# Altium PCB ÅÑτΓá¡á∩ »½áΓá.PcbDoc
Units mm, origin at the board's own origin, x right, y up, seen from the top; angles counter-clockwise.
Board outline 140 x 100 mm, 4 copper layers ([1]Top, [2]MWGND, [3]Signal, [4]Power), stack 1.271 mm thick; 48 components, 23 nets, 192 pads, 798 vias.
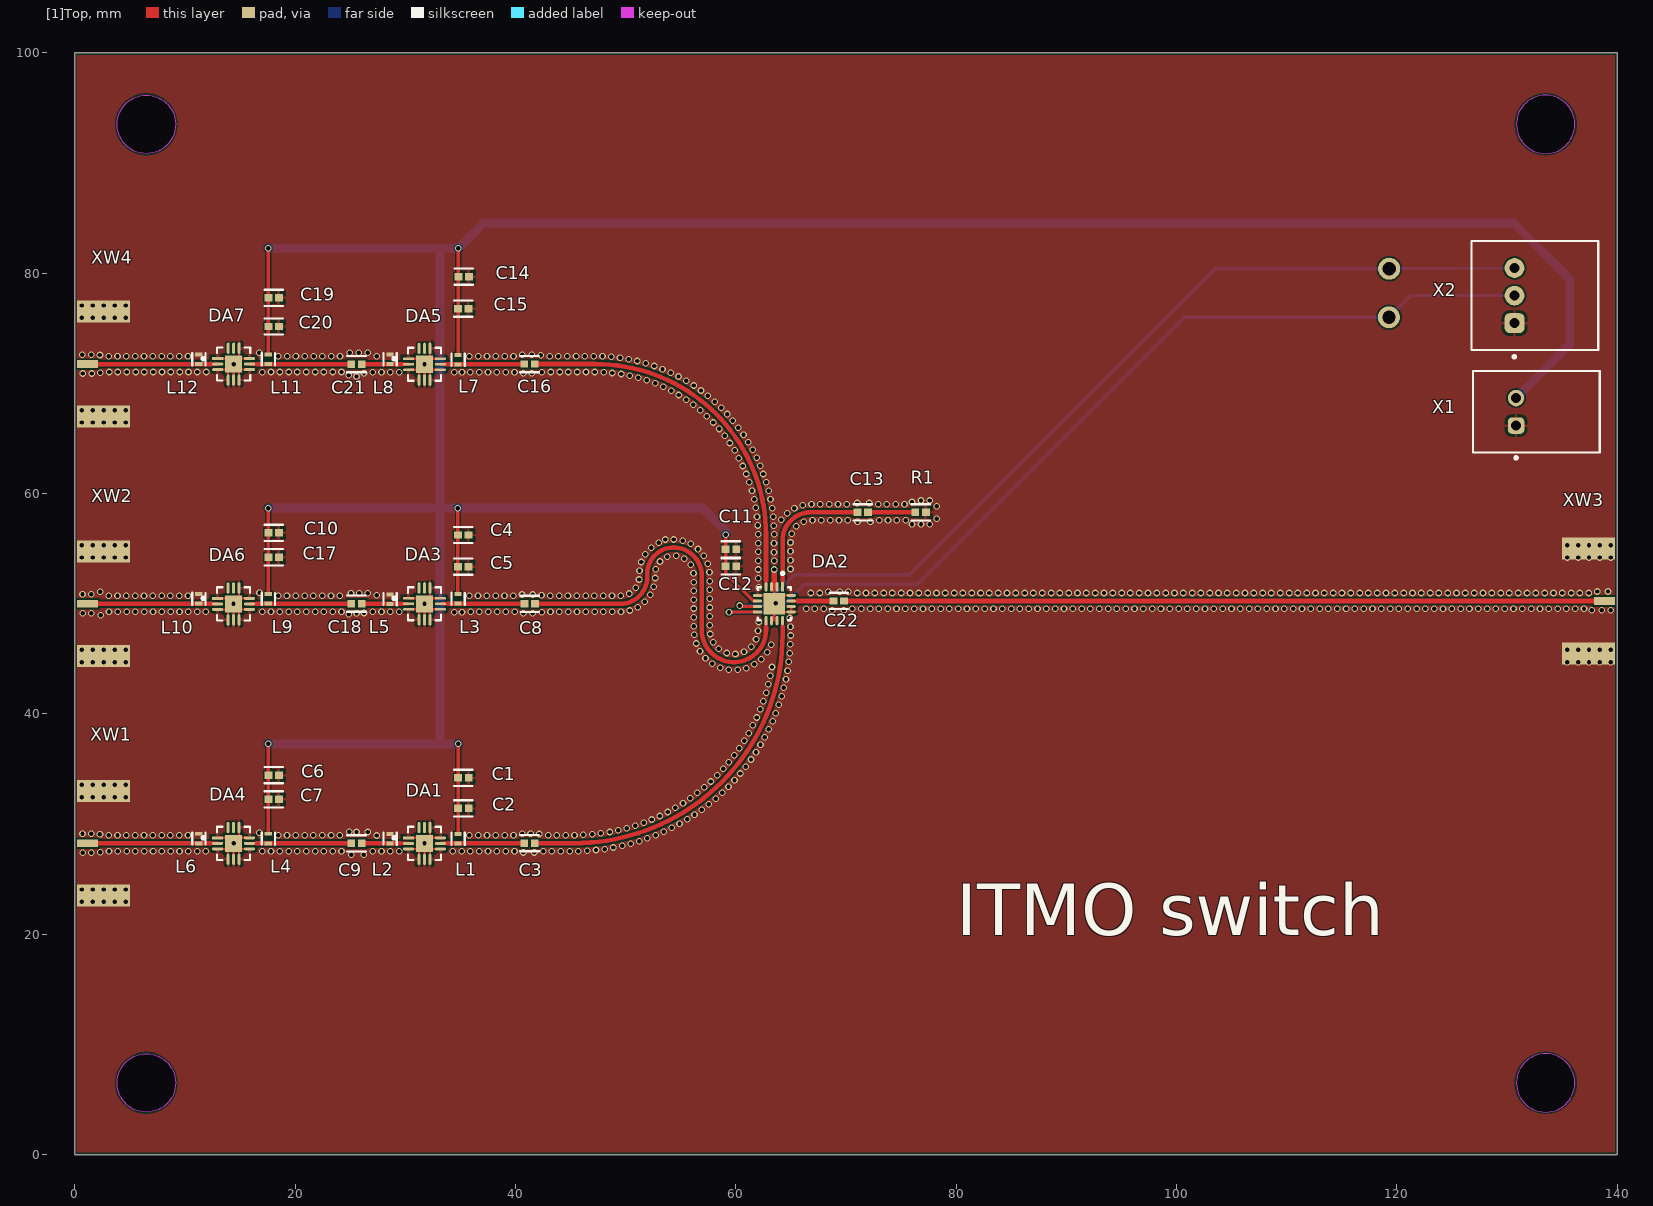
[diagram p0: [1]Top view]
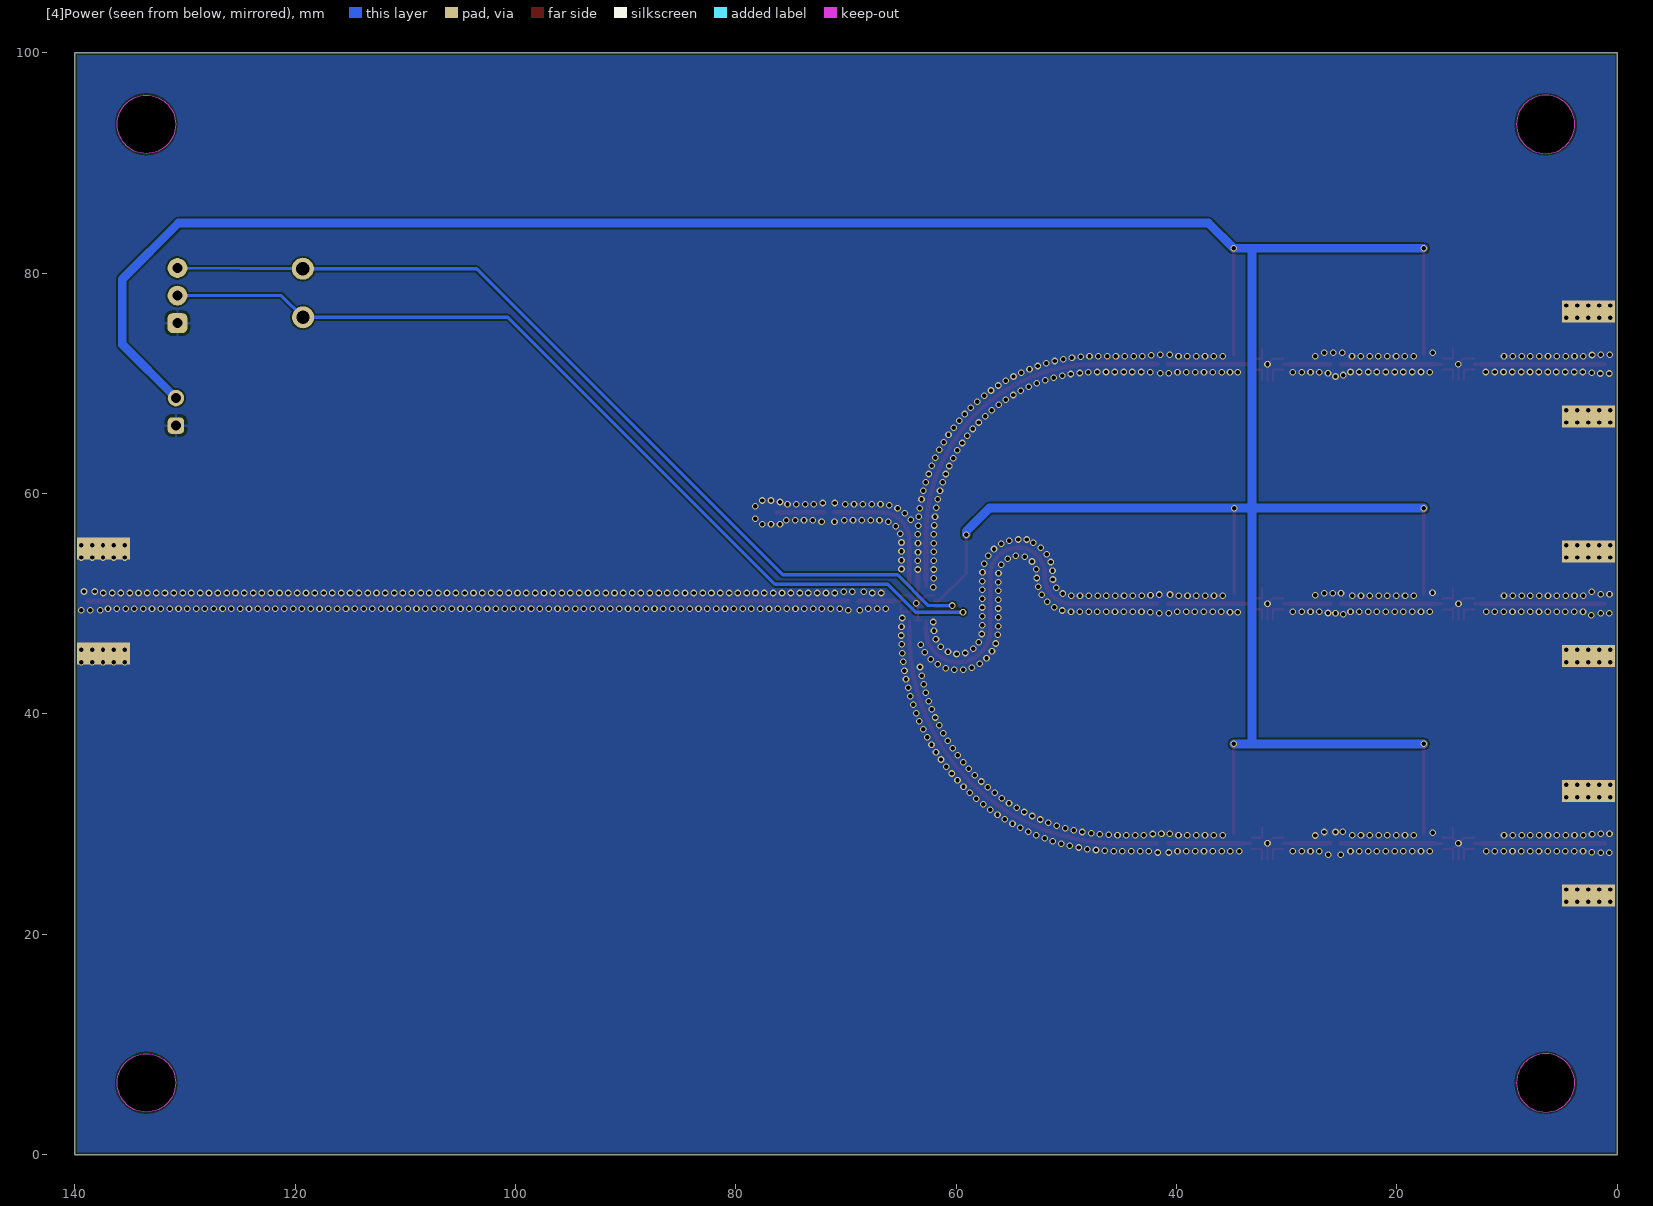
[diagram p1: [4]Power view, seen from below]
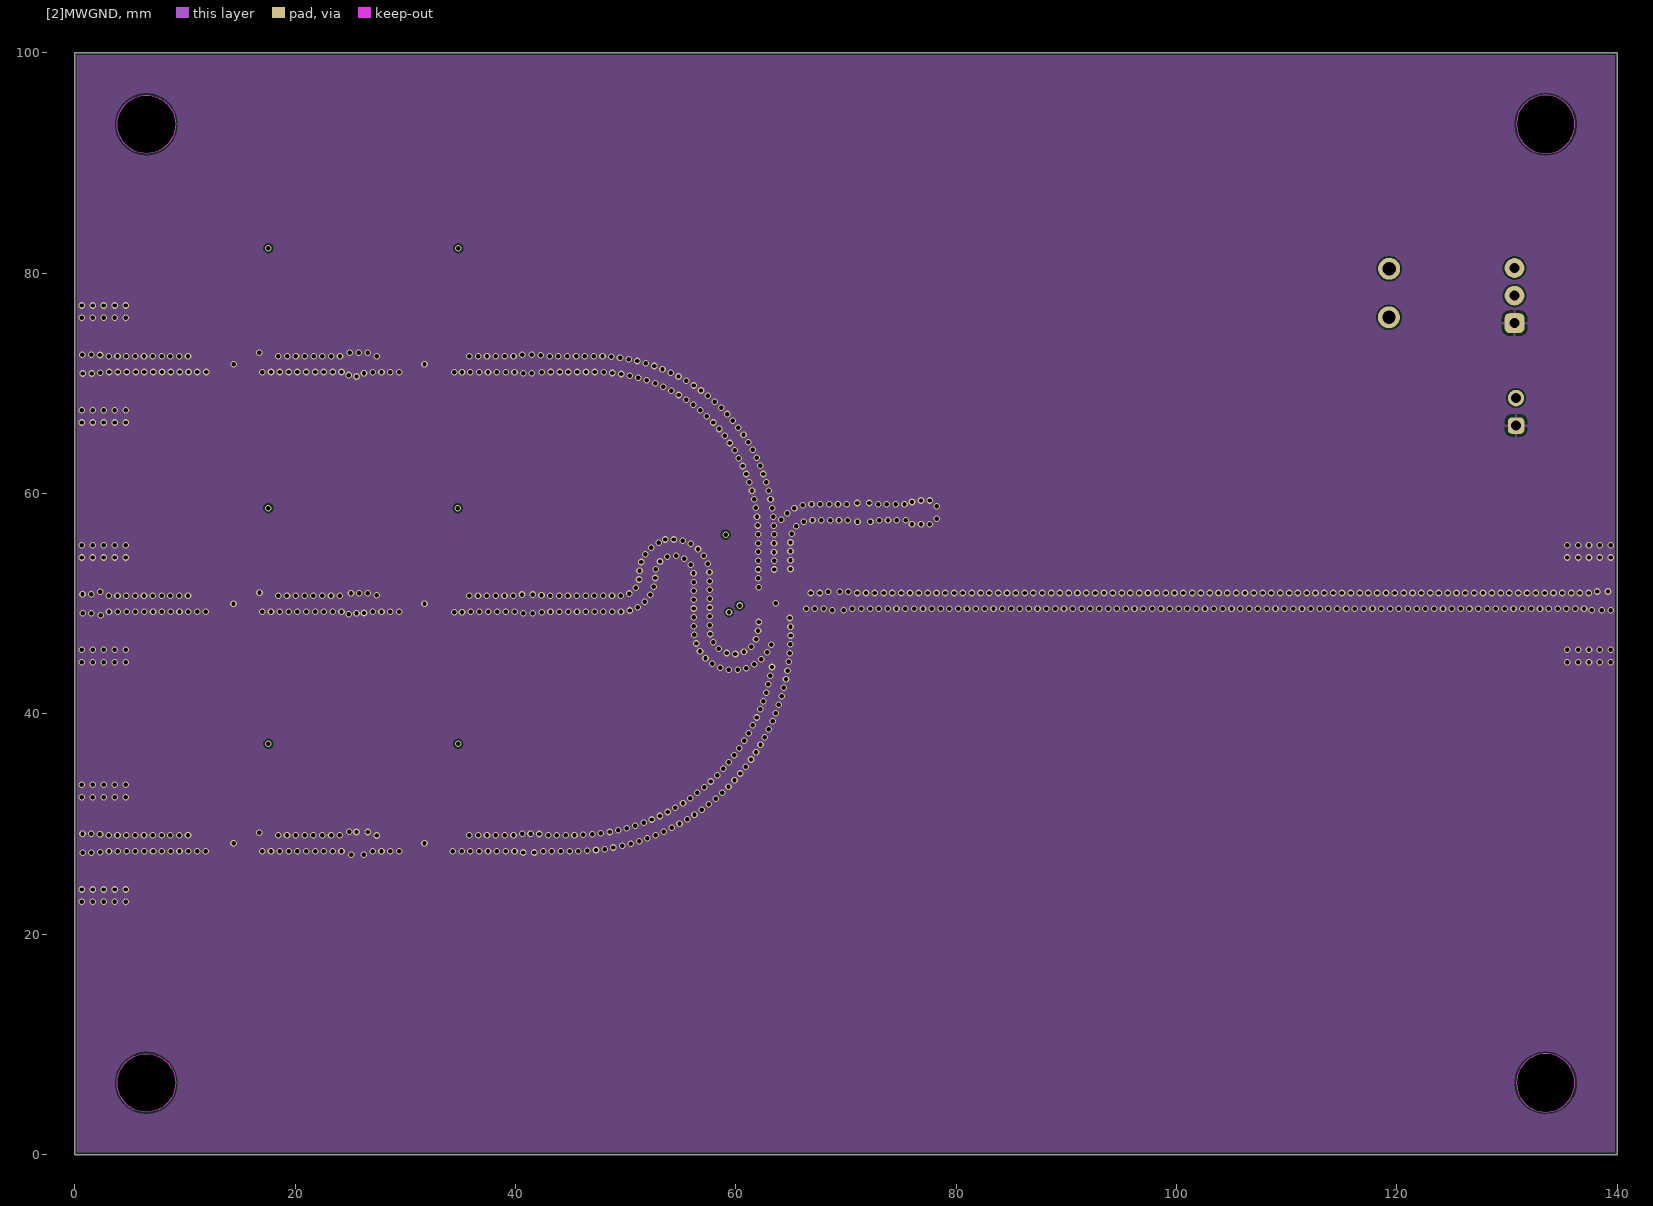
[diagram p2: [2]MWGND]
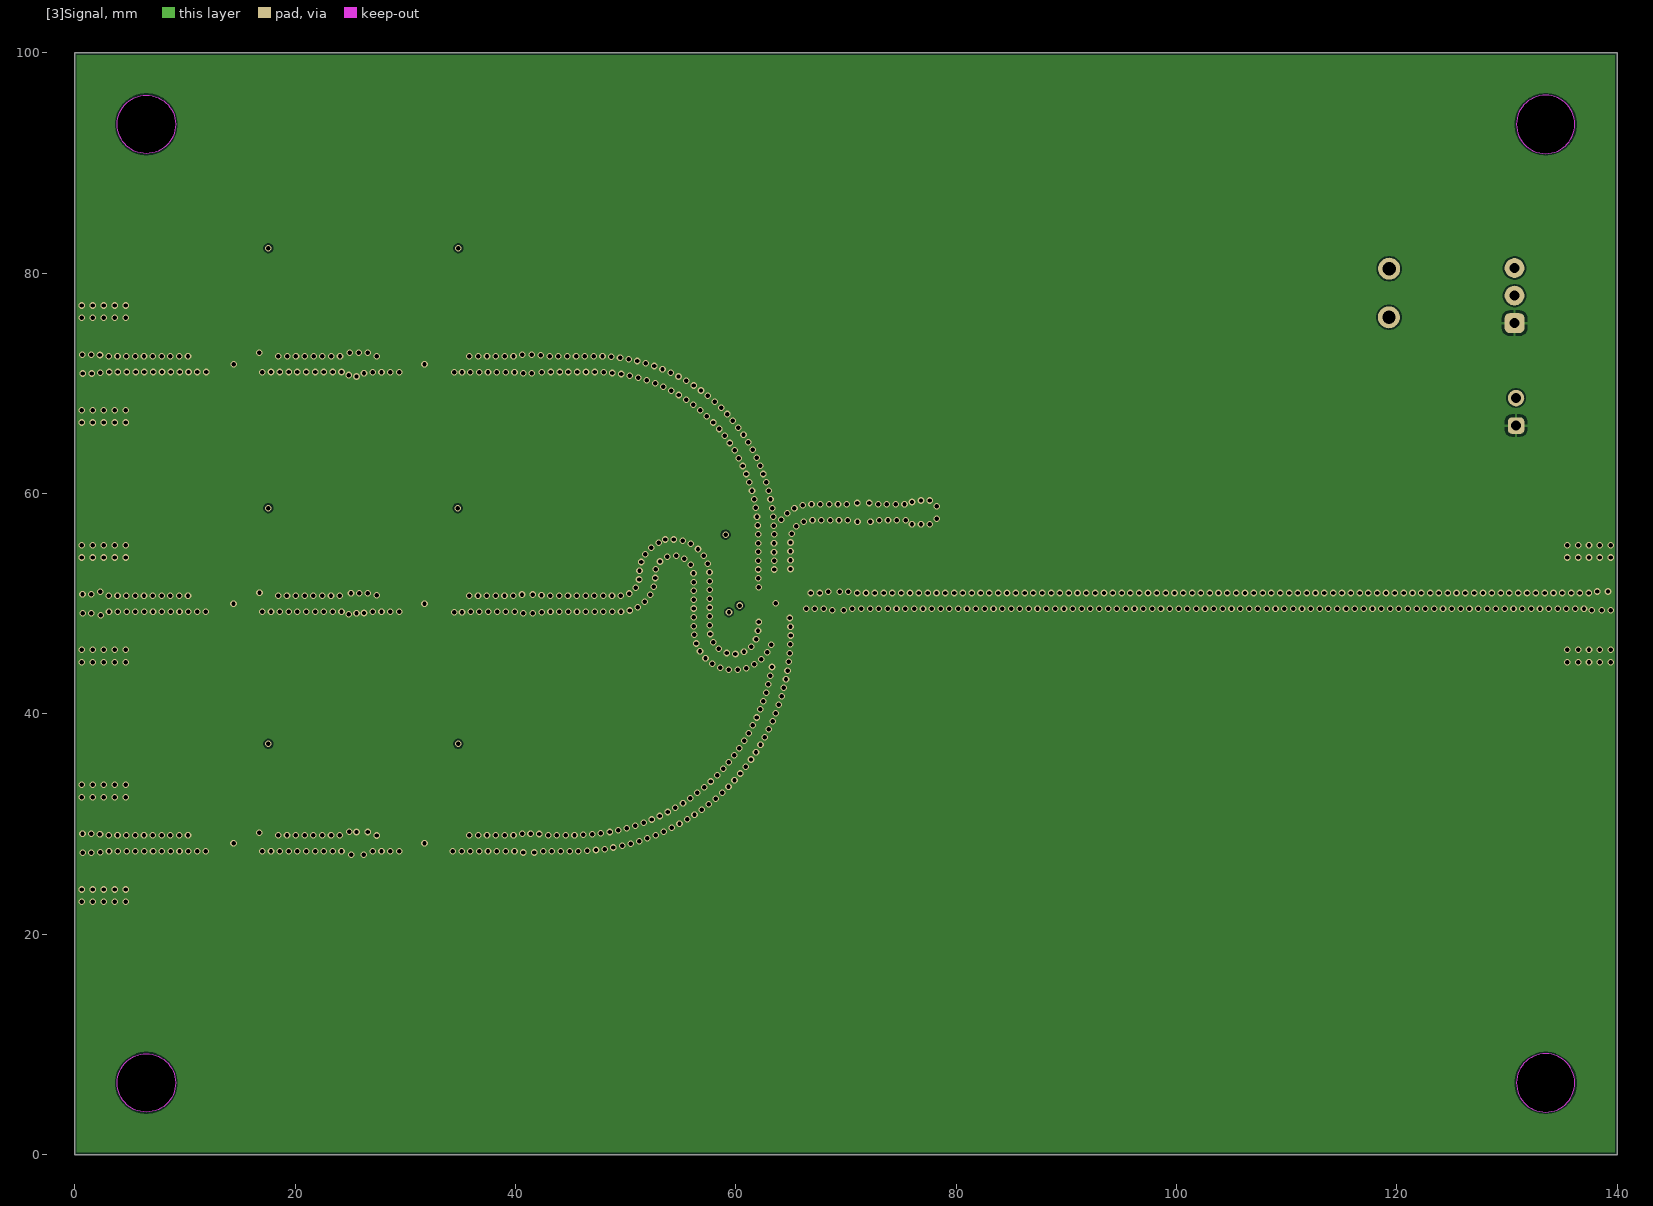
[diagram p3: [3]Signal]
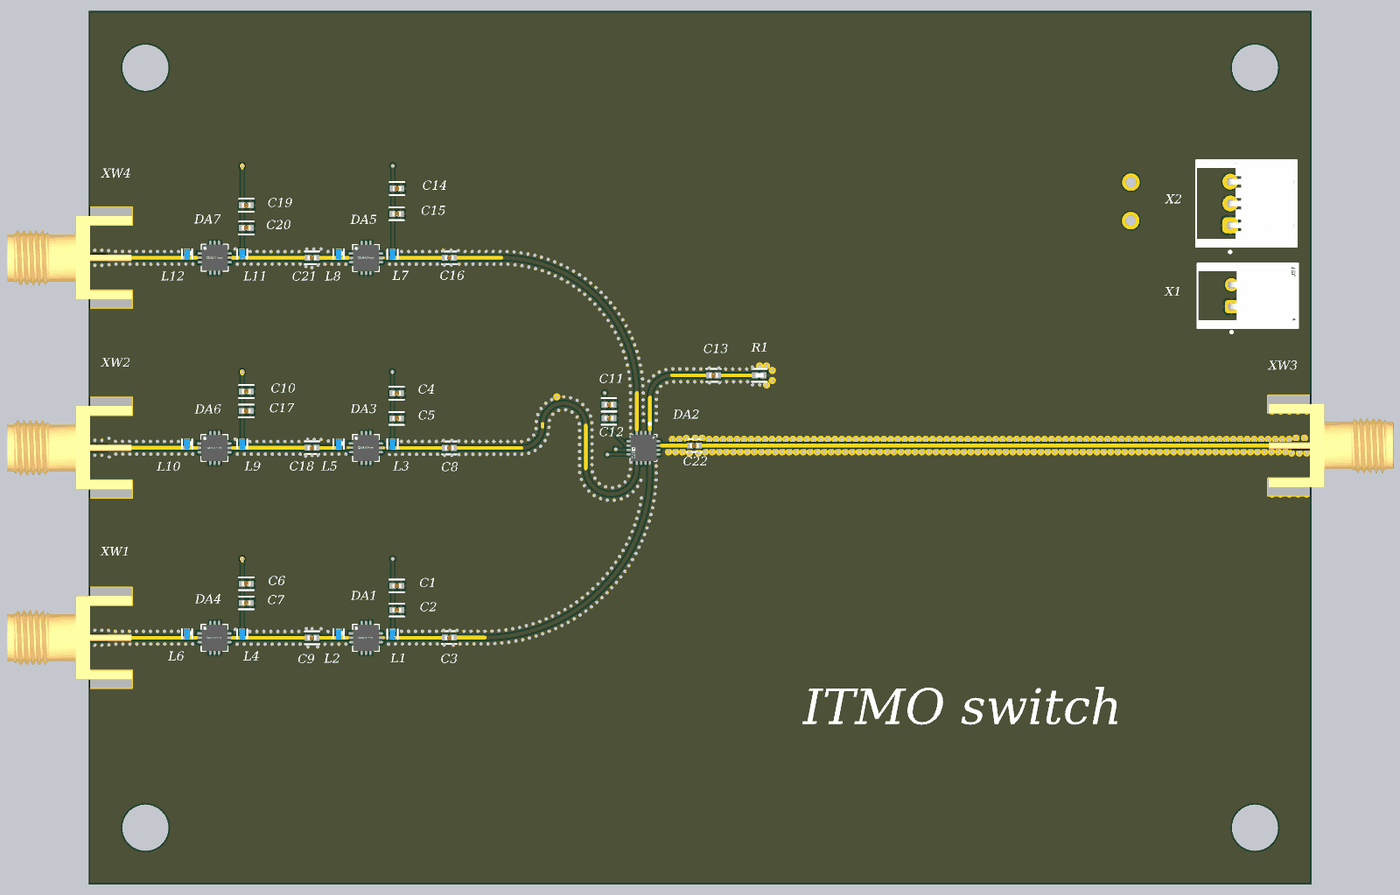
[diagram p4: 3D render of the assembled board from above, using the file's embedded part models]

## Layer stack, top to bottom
Top Solder: solder mask 0.0102, Solder Resist, Dk 3.5
[1]Top: signal copper 0.018
RO4003C: core 0.2032, Core-026, Dk 3.38
[2]MWGND: signal copper 0.018
Dielectric 1: prepreg 0.2083, PP-022, Dk 4.5
[3]Signal: signal copper 0.018
FR-4: core 0.7874, Core-040, Dk 4.6
[4]Power: signal copper 0.018
Bottom Solder: solder mask 0.0102, Solder Resist, Dk 3.5

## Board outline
0.006,0.006 140.006,0.006 140.006,100.006 0.006,100.006
cut-out: 6.506,3.856 cw(c6.506,6.506) 3.856,6.506 cw(c6.506,6.506) 6.506,9.156 cw(c6.506,6.506) 9.156,6.506 cw(c6.506,6.506)
cut-out: 130.856,6.506 ccw(c133.506,6.506) 133.506,3.856 ccw(c133.506,6.506) 136.156,6.506 ccw(c133.506,6.506) 133.506,9.156 ccw(c133.506,6.506)
cut-out: 130.856,93.506 ccw(c133.506,93.506) 133.506,90.856 ccw(c133.506,93.506) 136.156,93.506 ccw(c133.506,93.506) 133.506,96.156 ccw(c133.506,93.506)
cut-out: 6.506,90.856 cw(c6.506,93.506) 3.856,93.506 cw(c6.506,93.506) 6.506,96.156 cw(c6.506,93.506) 9.156,93.506 cw(c6.506,93.506)

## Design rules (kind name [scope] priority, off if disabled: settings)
Clearance CPWG_1 [InNetClass('RF') vs InNet('GND')] p1: gap=0.2 ignorepadtopadclearanceinfootprint=FALSE except(0.15: Arc-SMDPad Track-SMDPad SMDPad-SMDPad)
Clearance [All] p2: gap=0.15 ignorepadtopadclearanceinfootprint=FALSE
MatchedLengths lia_zochem_ti_umer [InNetClass('RF')] p1: tolerance=1 checknetsindiffpair=TRUE checkdiffpairvsdiffpair=FALSE checkxsignals=FALSE checkothers=FALSE
MinimumSolderMaskSliver [All] p1: minsoldermaskwidth=0.15
PolygonConnect RF_COMPONENTS [(HasFootprint('S-P2152-19CQA') OR HasFootprint('FP-0402HP-MFG')) vs InNet('GND')] p1: connectstyle=Direct reliefconductorwidth=0.254 reliefentries=4 polygonreliefangle="90 Angle" airgapwidth=0.15
PolygonConnect [All] p2: thpad.connectstyle=Relief thpad.reliefconductorwidth=0.254 thpad.reliefentries=4 thpad.polygonreliefangle="90 Angle" thpad.airgapwidth=0.254 smdpad.connectstyle=Relief smdpad.reliefconductorwidth=0.254 smdpad.reliefentries=4 smdpad.polygonreliefangle="90 Angle" smdpad.airgapwidth=0.254 via.connectstyle=Direct via.reliefconductorwidth=0.254 via.reliefentries=4 via.polygonreliefangle="90 Angle" via.airgapwidth=0.254
RoutingVias [All] p1: holewidth=0.4 width=0.6 viastyle="Through Hole" minholewidth=0.3 minwidth=0.5 maxholewidth=0.711 maxwidth=1
SolderMaskExpansion CPWG [InNetClass('RF')] p1: expansion=1 istentingtop=FALSE
SolderMaskExpansion [All] p2: expansion=0.102 istentingtop=FALSE
SupplyNets "Schematic Supply Nets_1" [InNet('+5')] p1: voltage=0.000
SupplyNets "Schematic Supply Nets" [InNet('GND')] p2: voltage=0.000
Width micro_strip [InNetClass('RF')] p1: maxlimit=0.5 minlimit=0.254 preferedwidth=0.254 toplayer_minwidth=0.418 toplayer_maxwidth=0.418 toplayer_prefwidth=0.418 impedanceprofiledriven=TRUE impedanceprofileid={426BE0D7-A08D-4F41-A99D-DD10C29EF04F} impedanceprofilevalue=50.000000 minimp=50.000000 maximp=50.000000 favimp=50.000000 checkconnectedcopper=TRUE
Width [All] p2: maxlimit=0.8 minlimit=0.2 preferedwidth=0.3
29 further rules are at their usual default settings.

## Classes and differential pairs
net class RF_SAME: NetC3_1 NetC8_1 NetC9_2 NetC18_2 NetC21_1 NetDA7_2
net class RF: NetC3_1 NetC3_2 NetC8_1 NetC8_2 NetC9_1 NetC9_2 NetC13_1 NetC13_2 NetC16_1 NetC16_2 NetC18_1 NetC18_2 NetC21_1 NetC21_2 NetC22_1 NetC22_2 NetDA4_2 NetDA6_2 NetDA7_2
component class AMP4: XW3
component class AMP3: DA5 XW4
component class AMP2: DA3 XW2
component class AMP1: DA1 DA4 DA6 DA7 XW1

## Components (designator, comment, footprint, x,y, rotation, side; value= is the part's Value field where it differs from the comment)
C1 "10pF" FP-GJM155-0_05-IPC_A 35.285,34.186 r0 top
C2 "10nF" FP-GJM155-0_05-IPC_A 35.285,31.417 r0 top
C3 "100 pF" FP-GJM155-0_05-IPC_A 41.279,28.268 r180 top
C4 "10pF" FP-GJM155-0_05-IPC_A 35.259,56.233 r0 top
C5 "10nF" FP-GJM155-0_05-IPC_A 35.259,53.363 r0 top
C6 "10pF" FP-GJM155-0_05-IPC_A 18.057,34.434 r0 top
C7 "10nF" FP-GJM155-0_05-IPC_A 18.057,32.244 r0 top
C8 "100pF" FP-GJM155-0_05-IPC_A 41.296,49.985 r180 top
C9 "100 pF" FP-GJM155-0_05-IPC_A 25.578,28.251 r180 top
C10 "10pF" FP-GJM155-0_05-IPC_A 18.057,56.437 r0 top
C11 "10 nF" FP-GJM155-0_05-IPC_A 59.563,54.938 r180 top
C12 "10 pF" FP-GJM155-0_05-IPC_A 59.563,53.388 r180 top
C13 "100pF" FP-GJM155-0_05-IPC_A 71.526,58.291 r180 top
C14 "10pF" FP-GJM155-0_05-IPC_A 35.302,79.677 r0 top
C15 "10nF" FP-GJM155-0_05-IPC_A 35.259,76.782 r0 top
C16 "100pF" FP-GJM155-0_05-IPC_A 41.279,71.753 r180 top
C17 "10nF" FP-GJM155-0_05-IPC_A 18.057,54.217 r0 top
C18 "100 pF" FP-GJM155-0_05-IPC_A 25.578,50 r180 top
C19 "10pF" FP-GJM155-0_05-IPC_A 18.057,77.764 r0 top
C20 "10nF" FP-GJM155-0_05-IPC_A 18.057,75.16 r0 top
C21 "100 pF" FP-GJM155-0_05-IPC_A 25.578,71.75 r180 top
C22 "100 pF" FP-GJM155-0_05-IPC_A 69.342,50.25 r180 top
DA1 "PMA3-83LN+" FP-DQ1225-IPC_A#1 31.751,28.25 r0 top
DA2 "HMC7992" FP-CP-16-38-IPC_A 63.5,50 r270 top
DA3 "PMA3-83LN+" FP-DQ1225-IPC_A#2 31.751,49.993 r0 top
DA4 "PMA3-83LN+" FP-DQ1225-IPC_A#3 14.42,28.251 r0 top
DA5 "PMA3-83LN+" FP-DQ1225-IPC_A#1 31.751,71.735 r0 top
DA6 "PMA3-83LN+" FP-DQ1225-IPC_A#2 14.419,49.987 r0 top
DA7 "PMA3-83LN+" FP-DQ1225-IPC_A#3 14.428,71.747 r0 top
L1 "39 nH" FP-0402HP-MFG#1 34.798,28.671 r90 top
L2 "18nH" FP-0402HP-MFG#1 28.626,28.677 r270 top
L3 "39nH" FP-0402HP-MFG#1 34.798,50.439 r90 top
L4 "39 nH" FP-0402HP-MFG#1 17.579,28.686 r90 top
L5 "18nF" FP-0402HP-MFG#1 28.626,50.417 r270 top
L6 "18nH" FP-0402HP-MFG#1 11.268,28.686 r270 top
L7 "39nH" FP-0402HP-MFG#1 34.798,72.156 r90 top
L8 "18nH" FP-0402HP-MFG#1 28.626,72.181 r270 top
L9 "39 nH" FP-0402HP-MFG#1 17.579,50.435 r90 top
L10 "18nH" FP-0402HP-MFG#1 11.268,50.435 r270 top
L11 "39 nH" FP-0402HP-MFG#2 17.579,72.185 r90 top
L12 "18nH" FP-0402HP-MFG#1 11.268,72.185 r270 top
R1 "100" FP-CR0402-IPC_A 76.775,58.291 r180 top
X1 "JST-2P" FP-S2B-XH-A-1_LF_SN-MFG 132.67,67.415 r270 top
X2 "JST-3P" FP-S3B-XH-A-1_LF_SN-MFG 132.535,77.965 r270 top
XW1 "SMA" S-P2152-19CQA 2.6,33 r180 top
XW2 "SMA" S-P2152-19CQA 2.6,54.75 r180 top
XW3 "SMA" S-P2152-19CQA 137.4,45.5 r0 top
XW4 "SMA" S-P2152-19CQA 2.6,76.5 r180 top

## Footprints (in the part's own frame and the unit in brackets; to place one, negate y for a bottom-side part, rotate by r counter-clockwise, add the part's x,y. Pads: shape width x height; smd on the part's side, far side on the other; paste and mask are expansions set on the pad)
FP-0402HP-MFG#1 [mm]
  rect 0.36x0.66 smd paste+0 mask+0: 1(-0.435,0) 2(0.435,0)
  silkscreen extent -0.56,-0.6 0.55,0.6, body extent -0.71,-0.46 0.71,0.46, height 0.25
FP-0402HP-MFG#2 [mm]
  rect 0.36x0.66 smd paste+0: 1(-0.435,0)
  rect 0.36x0.66 smd paste+0 mask+0: 2(0.435,0)
  silkscreen extent -0.56,-0.6 0.55,0.6, body extent -0.71,-0.46 0.71,0.46, height 0.25
FP-CP-16-38-IPC_A [mm]
  rect 0.846x0.242 smd paste+0 mask+0: 1(-1.533,0.75)
  rrect100% 0.846x0.242 smd paste+0 mask+0: 2(-1.533,0.25) 3(-1.533,-0.25) 4(-1.533,-0.75) 9(1.533,-0.75) 10(1.533,-0.25) 11(1.533,0.25) 12(1.533,0.75)
  rrect100% 0.242x0.846 smd paste+0 mask+0: 5(-0.75,-1.533) 6(-0.25,-1.533) 7(0.25,-1.533) 8(0.75,-1.533) 13(0.75,1.533) 14(0.25,1.533) 15(-0.25,1.533) 16(-0.75,1.533)
  rect 1.92x1.92 smd paste-1000 mask+0: 17(0,0)
  silkscreen extent -2.88,-1.5 1.5,1.5, body extent -2.46,-2.46 2.46,2.46, height 0.25
FP-CR0402-IPC_A [mm]
  rect 0.715x0.672 smd paste+0 mask+0: 1(-0.479,0) 2(0.479,0)
  silkscreen extent -0.84,-0.74 0.84,0.74, body extent -1.04,-0.54 1.04,0.54, height 0.25
FP-DQ1225-IPC_A#1 [mm]
  rect 1.019x0.262 smd paste+0 mask+0: 1(-1.447,0.5)
  rrect100% 1.019x0.262 smd paste+0: 2(-1.447,0)
  rrect100% 1.019x0.262 smd paste+0 mask+0: 3(-1.447,-0.5) 7(1.447,-0.5) 8(1.447,0) 9(1.447,0.5)
  rrect100% 0.262x1.019 smd paste+0 mask+0: 4(-0.5,-1.447) 5(0,-1.447) 6(0.5,-1.447) 10(0.5,1.447) 11(0,1.447) 12(-0.5,1.447)
  rect 1.549x1.549 smd paste-1000 mask+0: 13(0,0)
  silkscreen extent -2.88,-1.5 1.5,1.5, body extent -2.46,-2.46 2.46,2.46, height 0.25
FP-DQ1225-IPC_A#2 [mm]
  rect 1.019x0.262 smd paste+0 mask+0: 1(-1.447,0.5)
  rrect100% 1.019x0.262 smd paste+0 mask+0: 2(-1.447,0) 3(-1.447,-0.5) 7(1.447,-0.5) 8(1.447,0) 9(1.447,0.5)
  rrect100% 0.262x1.019 smd paste+0 mask+0: 4(-0.5,-1.447) 5(0,-1.447) 6(0.5,-1.447) 10(0.5,1.447) 11(0,1.447) 12(-0.5,1.447)
  rect 1.549x1.549 smd paste-1000 mask+0: 13(0,0)
  silkscreen extent -2.88,-1.5 1.5,1.5, body extent -2.46,-2.46 2.46,2.46, height 0.25
FP-DQ1225-IPC_A#3 [mm]
  rect 1.019x0.262 smd paste+0 mask+0: 1(-1.447,0.5)
  rrect100% 1.019x0.262 smd paste+0: 2(-1.447,0) 8(1.447,0)
  rrect100% 1.019x0.262 smd paste+0 mask+0: 3(-1.447,-0.5) 7(1.447,-0.5) 9(1.447,0.5)
  rrect100% 0.262x1.019 smd paste+0 mask+0: 4(-0.5,-1.447) 5(0,-1.447) 6(0.5,-1.447) 10(0.5,1.447) 11(0,1.447) 12(-0.5,1.447)
  rect 1.549x1.549 smd paste-1000 mask+0: 13(0,0)
  silkscreen extent -2.88,-1.5 1.5,1.5, body extent -2.46,-2.46 2.46,2.46, height 0.25
FP-GJM155-0_05-IPC_A [mm]
  rect 0.715x0.672 smd paste+0 mask+0: 1(-0.479,0) 2(0.479,0)
  silkscreen extent -0.84,-0.74 0.84,0.74, body extent -1.04,-0.54 1.04,0.54, height 0.25
FP-S2B-XH-A-1_LF_SN-MFG [mm]
  rrect50% 1.5x1.5 hole 0.9 paste-2539.97 mask+0: 1(1.25,-1.85)
  round 1.5 hole 0.9 paste-2539.97 mask+0: 2(-1.25,-1.85)
  silkscreen extent -3.7,-5.75 4.3,5.75, body extent -3.8,-5.85 3.8,5.85, height 0.25
FP-S3B-XH-A-1_LF_SN-MFG [mm]
  rrect50% 1.8x1.8 hole 0.9 paste-2539.97 mask+0: 1(2.5,-1.85)
  round 1.8 hole 0.9 paste-2539.97 mask+0: 2(0,-1.85) 3(-2.5,-1.85)
  silkscreen extent -4.95,-5.75 5.67,5.75, body extent -5.05,-5.85 5.05,5.85, height 0.25
S-P2152-19CQA [mm]
  rect 1.9x0.7 smd: 1(1.45,4.75)
  rect 4.8x2 smd: 2(0,9.5) 2(0,0)
  rect 4.8x2 smd far side: 2(0,9.5) 2(0,0)
  body extent -2.34,-0.02 11.94,9.51, height 4.8

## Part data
C1 C2 C3 C4 C5 C6 C7 C8 C9 C10 C11 C12 C13 C14 C15 C16 C17 C18 C19 C20 C21 C22: library part C
L1 L2 L3 L4 L5 L6 L7 L8 L9 L10 L11 L12: library part L
R1: library part R
X1 X2: "JST type connector"

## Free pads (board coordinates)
  round 2 hole 1.2 paste-2539.97 mask+0: MH5(119.305,80.405) MH6(119.28,75.995)

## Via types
v1: diameter 0.6, hole 0.4, [1]Top to [4]Power, 792 vias
v2: diameter 0.6, hole 0.4, [1]Top to [4]Power, tented both sides, 6 vias

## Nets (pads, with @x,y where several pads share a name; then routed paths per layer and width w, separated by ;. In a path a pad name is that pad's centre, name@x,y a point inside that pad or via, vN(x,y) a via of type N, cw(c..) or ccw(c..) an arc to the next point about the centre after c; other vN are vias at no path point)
+5: C1.1 C2.1 C4.1 C5.1 C6.1 C7.1 C10.1 C11.2 C12.2 C14.1 C15.1 C17.1 C19.1 C20.1 DA2.6 L1.2 L3.2 L4.2 L7.2 L9.2 L11.2 X1.2 | length 297.6
  [1]Top w0.3: L4.2 v1(17.579,37.275) ; L9.2 v1(17.579,58.675) ; L11.2 v1(17.579,82.26) ; v2(34.765,58.675) 34.782,58.659 34.782,50.89 L3.2 ; L1.2 34.807,29.115 34.807,37.267 v2(34.815,37.275) ; L7.2 34.811,72.603 34.811,82.247 v2(34.823,82.26) ; v2(59.084,56.268) C11.2 59.084,52.735 61.569,50.25 DA2.6
  [4]Power w0.8: v1(17.579,37.275) 33.15,37.275 ; v1(17.579,58.675) 33.15,58.675 ; v1(17.579,82.26) 33.15,82.26 ; v2(34.815,37.275) 33.15,37.275 ; v2(59.084,56.268) 59.084,56.581 56.99,58.675 v2(34.765,58.675) 33.15,58.675 ; X1.2 135.695,73.54 135.695,79.445 130.583,84.557 37.12,84.557 v2(34.823,82.26) 33.15,82.26 ; 33.15,37.275 33.15,58.675 ; 33.15,58.675 33.15,82.26
A: DA2.8 pad.MH6 X2.2 | length 85.8
  [1]Top w0.254: v2(59.385,49.223) 59.407,49.244 61.961,49.244 DA2.8
  [4]Power w0.3: v2(59.385,49.223) 63.679,49.223 66.221,51.765 76.455,51.765 100.685,75.995 pad.MH6 121.25,77.965 X2.2
B: DA2.7 pad.MH5 X2.3 | length 84.6
  [1]Top w0.254: v2(60.35,49.832) 60.444,49.832 60.526,49.75 DA2.7
  [4]Power w0.3: v2(60.35,49.832) 62.534,49.832 65.327,52.625 75.76,52.625 103.54,80.405 pad.MH5 X2.3
GND: C1.2 C2.2 C4.2 C5.2 C6.2 C7.2 C10.2 C11.1 C12.1 C14.2 C15.2 C17.2 C19.2 C20.2 DA1.1 DA1.3 DA1.4 DA1.5 DA1.6 DA1.7 DA1.9 DA1.10 DA1.13 DA2.2 DA2.3 DA2.5 DA2.10 DA2.11 DA2.13 DA2.14 DA2.16 DA2.17 DA3.1 DA3.3 DA3.4 DA3.5 DA3.6 DA3.7 DA3.9 DA3.10 DA3.13 DA4.1 DA4.3 DA4.4 DA4.5 DA4.6 DA4.7 DA4.9 DA4.10 DA4.13 DA5.1 DA5.3 DA5.4 DA5.5 DA5.6 DA5.7 DA5.9 DA5.10 DA5.13 DA6.1 DA6.3 DA6.4 DA6.5 DA6.6 DA6.7 DA6.9 DA6.10 DA6.13 DA7.1 DA7.3 DA7.4 DA7.5 DA7.6 DA7.7 DA7.9 DA7.10 DA7.13 L2.1 L5.1 L6.1 L8.1 L10.1 L12.1 R1.1 X1.1 X2.1 XW1.2 XW2.2 XW3.2 XW4.2 | length 66.3
  [1]Top w0.2: DA6.3 13.919,49.487 DA6.4 ; DA6.1 13.919,50.487 v1(14.419,49.987) ; DA4.3 DA4.13@13.92,27.751 ; DA4.1 13.92,28.751 v1(14.42,28.251) ; DA7.3 13.928,71.247 DA7.4 ; DA7.1 13.928,72.247 v1(14.428,71.747) DA7.5 ; DA4.4 DA4.13@13.92,27.751 ; DA6.5 v1(14.419,49.987) ; DA4.5 v1(14.42,28.251) ; DA6.6 DA6.13@14.919,49.487 ; DA6.10 14.919,50.487 DA6.9 ; DA4.6 DA4.13@14.92,27.751 ; DA4.10 DA4.13@14.92,28.751 ; DA7.6 14.928,71.247 DA7.7 ; DA7.10 14.928,72.247 DA7.9 ; DA6.7 DA6.13@14.919,49.487 ; DA4.7 DA4.13@14.92,27.751 ; DA4.9 DA4.13@14.92,28.751 ; DA1.3 31.251,27.75 DA1.4 ; DA1.1 31.251,28.75 v1(31.751,28.25) DA1.5 ; DA3.3 31.251,49.493 DA3.4 ; DA3.1 31.251,50.493 v1(31.751,49.993) DA3.5 ; DA5.3 31.251,71.235 DA5.4 ; DA5.1 31.251,72.235 v1(31.751,71.735) DA5.5 ; DA1.6 32.251,27.75 DA1.7 ; DA1.10 32.251,28.75 DA1.9 ; DA3.6 32.251,49.493 DA3.7 ; DA3.10 32.251,50.493 DA3.9 ; DA5.6 32.251,71.235 DA5.7 ; DA5.10 32.251,72.235 DA5.9 ; DA2.5 62.75,50.75 DA2.17 64.25,50.75 DA2.16 ; DA2.10 63.5,48.467 ; DA2.17@63.5,49.892 63.5,48.467 ; DA2.17@63.5,50.185 63.5,51.533 ; DA2.17@63.554,49.946 64.25,49.25 DA2.13 DA2.14 ; DA2.11 63.5,48.467 ; DA4.13@13.92,27.751 v1(14.42,28.251) ; v1(14.419,49.987) DA6.13@14.919,49.487 ; v1(14.42,28.251) DA4.13@14.92,27.751 ; v1(14.42,28.251) DA4.13@14.92,28.751
  [1]Top w0.5: 63.5,51.533 v1(63.5,53.104)
  other v1: 0.66,22.946 1.651,22.946 2.642,22.946 3.632,22.946 4.623,22.946 0.66,24.064 1.651,24.064 2.642,24.064 3.632,24.064 4.623,24.064 25.099,27.222 26.233,27.222 0.72,27.39 1.52,27.39 2.318,27.445 40.71,27.422 41.727,27.422 27.049,27.519 27.849,27.519 3.114,27.527 3.914,27.527 4.714,27.527 5.514,27.527 6.314,27.527 7.114,27.527 7.914,27.527 8.714,27.527 9.514,27.527 10.314,27.527 11.114,27.527 11.914,27.532 17.018,27.524 17.818,27.528 18.618,27.528 19.418,27.528 20.218,27.528 21.018,27.528 21.818,27.528 22.618,27.528 23.418,27.528 24.218,27.528 28.649,27.524 29.449,27.527 34.318,27.527 35.118,27.536 35.918,27.536 36.718,27.536 37.518,27.536 38.318,27.536 39.118,27.536 39.918,27.536 42.517,27.545 43.317,27.545 44.117,27.545 44.917,27.545 45.717,27.55 46.517,27.578 47.314,27.647 48.109,27.732 48.897,27.872 49.682,28.025 50.457,28.223 51.225,28.446 51.985,28.698 27.404,28.965 3.089,28.973 3.889,28.973 4.689,28.973 5.489,28.973 6.289,28.973 7.089,28.973 7.889,28.973 8.689,28.973 9.489,28.973 10.289,28.973 18.47,28.974 19.27,28.974 20.07,28.974 20.87,28.974 21.67,28.974 22.47,28.974 23.27,28.974 24.07,28.974 35.825,28.982 36.625,28.982 37.425,28.982 38.225,28.982 39.025,28.982 39.825,28.982 42.968,28.991 43.768,28.991 44.568,28.991 45.368,28.988 52.73,28.989 46.168,29.017 46.966,29.068 2.295,29.071 0.713,29.11 1.513,29.11 40.615,29.114 41.376,29.109 42.176,29.102 47.761,29.154 16.768,29.216 25.578,29.279 26.614,29.279 48.551,29.283 53.469,29.295 24.919,29.31 49.336,29.434 50.112,29.632 54.186,29.65 50.879,29.859 54.896,30.018 51.638,30.111 52.379,30.413 55.584,30.427 53.111,30.734 56.259,30.857 53.827,31.092 56.916,31.313 54.524,31.484 57.549,31.801 55.211,31.895 58.172,32.303 55.868,32.351 0.66,32.446 1.651,32.446 2.642,32.446 3.632,32.446 4.623,32.446 56.511,32.827 58.76,32.846 57.134,33.329 59.338,33.399 0.66,33.564 1.651,33.564 2.642,33.564 3.632,33.564 4.623,33.564 57.727,33.866 59.883,33.985 58.305,34.418 60.409,34.587 58.85,35.004 60.911,35.21 59.372,35.611 61.382,35.857 59.874,36.234 61.838,36.514 60.333,36.889 62.249,37.2 60.774,37.556 62.648,37.894 61.182,38.244 63.006,38.609 61.556,38.952 63.342,39.336 61.91,39.669 63.648,40.075 62.216,40.408 63.917,40.828 62.498,41.157 64.17,41.587 62.751,41.916 64.371,42.361 62.958,42.688 64.559,43.139 63.144,43.466 64.701,43.926 59.377,44.005 60.177,43.996 60.96,44.156 58.599,44.191 63.287,44.254 61.688,44.49 57.882,44.546 0.66,44.696 1.651,44.696 2.642,44.696 3.632,44.696 4.623,44.696 135.459,44.696 136.45,44.696 137.44,44.696 138.431,44.696 139.422,44.696 64.819,44.717 62.329,44.968 57.255,45.044 59.973,45.435 59.178,45.525 64.904,45.513 62.847,45.578 60.749,45.631 56.758,45.67 0.66,45.814 1.651,45.814 2.642,45.814 3.632,45.814 4.623,45.814 135.459,45.814 136.45,45.814 137.44,45.814 138.431,45.814 139.422,45.814 58.472,45.902 61.403,46.091 63.217,46.287 64.951,46.312 56.403,46.387 57.947,46.505 61.843,46.759 64.979,47.111 56.217,47.165 57.668,47.255 62.019,47.54 64.973,47.911 56.189,47.965 57.634,48.054 62.077,48.337 64.891,48.707 56.189,48.765 57.634,48.854 2.362,48.946 24.867,49.047 25.578,49.13 0.718,49.14 1.518,49.14 26.257,49.154 40.728,49.139 41.593,49.139 34.443,49.215 35.153,49.215 42.389,49.219 43.188,49.262 43.988,49.262 44.788,49.262 45.588,49.262 46.388,49.262 47.188,49.262 47.988,49.262 48.788,49.262 49.588,49.261 3.112,49.277 3.912,49.277 4.712,49.277 5.512,49.277 6.312,49.277 7.112,49.277 7.912,49.277 8.712,49.277 9.512,49.277 10.312,49.277 11.112,49.277 11.912,49.273 17.018,49.274 17.818,49.277 18.618,49.277 19.418,49.277 20.218,49.277 21.018,49.277 21.818,49.277 22.618,49.277 23.418,49.277 24.218,49.277 27.048,49.268 27.848,49.268 28.648,49.268 29.448,49.284 35.938,49.266 36.738,49.266 37.538,49.266 38.338,49.266 39.138,49.266 39.938,49.266 50.379,49.38 137.7,49.39 138.582,49.39 139.422,49.39 68.773,49.404 69.8,49.404 66.383,49.527 67.183,49.527 67.983,49.527 70.591,49.527 71.391,49.527 72.191,49.527 72.991,49.527 73.791,49.527 74.591,49.527 75.391,49.527 76.191,49.527 76.991,49.527 77.791,49.527 78.591,49.527 79.391,49.527 80.191,49.527 80.991,49.527 81.791,49.527 82.591,49.527 83.391,49.527 84.191,49.527 84.991,49.527 85.791,49.527 86.591,49.527 87.391,49.527 88.191,49.527 88.991,49.527 89.791,49.527 90.591,49.527 91.391,49.527 92.191,49.527 92.991,49.527 93.791,49.527 94.591,49.527 95.391,49.527 96.191,49.527 96.991,49.527 97.791,49.527 98.591,49.527 99.391,49.527 100.191,49.527 100.991,49.527 101.791,49.527 102.591,49.527 103.391,49.527 104.191,49.527 104.991,49.527 105.791,49.527 106.591,49.527 107.391,49.527 108.191,49.527 108.991,49.527 109.791,49.527 110.591,49.527 111.391,49.527 112.191,49.527 112.991,49.527 113.791,49.527 114.591,49.527 115.391,49.527 116.191,49.527 116.991,49.527 117.791,49.527 118.591,49.527 119.391,49.527 120.191,49.527 120.991,49.527 121.791,49.527 122.591,49.527 123.391,49.527 124.191,49.527 124.991,49.527 125.791,49.527 126.591,49.527 127.391,49.527 128.191,49.527 128.991,49.527 129.791,49.527 130.591,49.527 131.391,49.527 132.191,49.527 132.991,49.527 133.791,49.527 134.591,49.527 135.391,49.527 136.191,49.527 136.991,49.527 56.189,49.565 57.634,49.654 51.116,49.692 63.646,50.039 51.753,50.176 56.189,50.365 57.634,50.454 43.17,50.708 43.97,50.708 44.77,50.708 45.57,50.708 46.37,50.708 47.17,50.708 47.97,50.708 48.77,50.708 3.089,50.723 3.889,50.723 4.689,50.723 5.489,50.723 6.289,50.723 7.089,50.723 7.889,50.723 8.689,50.723 9.489,50.723 10.289,50.723 18.467,50.723 19.267,50.723 20.067,50.723 20.867,50.723 21.667,50.723 22.467,50.723 23.267,50.723 24.067,50.723 35.809,50.712 36.609,50.712 37.409,50.712 38.209,50.712 39.009,50.712 39.809,50.712 49.57,50.712 27.432,50.775 42.372,50.762 52.243,50.808 40.6,50.831 41.575,50.831 0.715,50.86 1.515,50.86 50.342,50.922 25.078,50.962 25.832,50.962 26.614,50.962 16.775,50.978 66.818,50.973 67.618,50.973 71.019,50.973 71.819,50.973 72.619,50.973 73.419,50.973 74.219,50.973 75.019,50.973 75.819,50.973 76.619,50.973 77.419,50.973 78.219,50.973 79.019,50.973 79.819,50.973 80.619,50.973 81.419,50.973 82.219,50.973 83.019,50.973 83.819,50.973 84.619,50.973 85.419,50.973 86.219,50.973 87.019,50.973 87.819,50.973 88.619,50.973 89.419,50.973 90.219,50.973 91.019,50.973 91.819,50.973 92.619,50.973 93.419,50.973 94.219,50.973 95.019,50.973 95.819,50.973 96.619,50.973 97.419,50.973 98.219,50.973 99.019,50.973 99.819,50.973 100.619,50.973 101.419,50.973 102.219,50.973 103.019,50.973 103.819,50.973 104.619,50.973 105.419,50.973 106.219,50.973 107.019,50.973 107.819,50.973 108.619,50.973 109.419,50.973 110.219,50.973 111.019,50.973 111.819,50.973 112.619,50.973 113.419,50.973 114.219,50.973 115.019,50.973 115.819,50.973 116.619,50.973 117.419,50.973 118.219,50.973 119.019,50.973 119.819,50.973 120.619,50.973 121.419,50.973 122.219,50.973 123.019,50.973 123.819,50.973 124.619,50.973 125.418,50.973 126.218,50.973 127.018,50.973 127.818,50.973 128.618,50.973 129.418,50.973 130.218,50.973 131.018,50.973 131.818,50.973 132.618,50.973 133.418,50.973 134.218,50.973 135.018,50.973 135.818,50.973 136.618,50.973 137.418,50.973 2.337,51.079 68.411,51.077 69.427,51.088 70.227,51.086 138.207,51.11 139.167,51.11 56.189,51.165 57.634,51.254 50.941,51.452 62.084,51.506 52.565,51.54 56.189,51.965 57.634,52.054 51.223,52.201 62.027,52.304 52.69,52.331 56.167,52.764 57.616,52.854 51.262,53 62.027,53.104 52.749,53.128 64.973,53.153 55.904,53.52 57.449,53.636 51.432,53.782 53.128,53.833 62.027,53.904 63.5,53.904 64.973,53.953 55.342,54.089 0.66,54.196 1.651,54.196 2.642,54.196 3.632,54.196 4.623,54.196 135.459,54.196 136.45,54.196 137.44,54.196 138.431,54.196 139.422,54.196 53.793,54.278 54.589,54.359 57.09,54.351 51.794,54.495 63.473,54.686 62.027,54.704 64.973,54.753 56.572,54.961 52.338,55.082 0.66,55.314 1.651,55.314 2.642,55.314 3.632,55.314 4.623,55.314 135.459,55.314 136.45,55.314 137.44,55.314 138.431,55.314 139.422,55.314 55.923,55.428 62.027,55.504 63.473,55.486 53.007,55.52 64.973,55.553 55.177,55.719 53.598,55.83 54.385,55.83 63.48,56.286 62.029,56.304 65.081,56.345 65.498,57.028 63.449,57.086 61.997,57.103 75.997,57.201 76.81,57.201 77.597,57.201 66.175,57.454 71.048,57.445 72.225,57.445 66.967,57.568 67.767,57.568 68.567,57.568 69.367,57.568 70.167,57.568 73.016,57.568 73.816,57.568 74.616,57.568 75.416,57.568 64.122,57.633 78.257,57.7 63.391,57.884 61.929,57.9 64.665,58.221 63.297,58.678 65.328,58.668 61.826,58.693 78.257,58.852 66.083,58.932 66.879,59.013 67.679,59.013 68.479,59.013 69.279,59.013 70.079,59.013 72.919,59.014 73.719,59.014 74.519,59.014 75.319,59.014 71.026,59.137 72.128,59.137 75.997,59.233 76.81,59.37 77.597,59.37 63.151,59.465 61.67,59.478 61.471,60.253 62.98,60.246 61.239,61.019 62.763,61.016 60.962,61.769 62.506,61.774 60.639,62.501 62.226,62.523 60.284,63.218 61.891,63.25 59.893,63.916 61.529,63.963 59.454,64.585 61.138,64.661 58.986,65.233 60.7,65.33 58.491,65.861 60.24,65.985 0.66,66.446 1.651,66.446 2.642,66.446 3.632,66.446 4.623,66.446 57.948,66.449 59.745,66.613 57.379,67.012 59.216,67.213 56.787,67.55 0.66,67.564 1.651,67.564 2.642,67.564 3.632,67.564 4.623,67.564 58.668,67.796 56.159,68.045 58.08,68.339 55.506,68.507 57.471,68.858 54.833,68.941 54.135,69.332 56.843,69.353 53.415,69.68 56.18,69.801 52.681,69.997 55.503,70.228 51.93,70.274 51.162,70.499 54.805,70.619 25.578,70.625 50.386,70.69 24.874,70.753 49.601,70.846 0.733,70.89 1.533,70.89 26.258,70.904 40.71,70.907 41.499,70.907 2.331,70.953 48.807,70.942 54.086,70.968 48.009,71.003 3.128,71.027 3.928,71.027 4.728,71.027 5.527,71.027 6.327,71.027 7.127,71.027 7.927,71.027 8.727,71.027 9.527,71.027 10.327,71.027 11.127,71.027 11.927,71.031 17.018,71.024 17.818,71.027 18.618,71.027 19.418,71.027 20.218,71.027 21.018,71.027 21.818,71.027 22.618,71.027 23.418,71.027 24.218,71.027 27.049,71.02 27.849,71.02 28.649,71.023 29.449,71.02 34.443,71.021 35.153,71.021 35.918,71.021 36.718,71.021 37.518,71.021 38.318,71.021 39.118,71.021 39.918,71.021 42.41,71.012 43.21,71.03 44.01,71.03 44.81,71.03 45.61,71.03 46.41,71.03 47.21,71.03 53.355,71.294 52.604,71.571 51.842,71.814 51.072,72.031 50.288,72.188 49.499,72.321 48.704,72.415 3.089,72.473 3.889,72.473 4.689,72.473 5.489,72.473 6.289,72.473 7.089,72.473 7.889,72.473 8.689,72.473 9.489,72.473 10.289,72.473 18.484,72.473 19.284,72.473 20.084,72.473 20.884,72.473 21.684,72.473 22.484,72.473 23.284,72.473 24.084,72.473 27.404,72.466 35.826,72.467 36.626,72.467 37.426,72.467 38.226,72.467 39.026,72.467 39.826,72.467 43.106,72.475 43.906,72.475 44.706,72.475 45.506,72.475 46.306,72.475 47.106,72.475 47.906,72.459 2.295,72.571 42.31,72.56 40.615,72.599 41.499,72.599 0.699,72.61 1.499,72.61 16.768,72.774 24.964,72.764 25.776,72.764 26.614,72.764 0.66,75.946 1.651,75.946 2.642,75.946 3.632,75.946 4.623,75.946 0.66,77.064 1.651,77.064 2.642,77.064 3.632,77.064 4.623,77.064
NetC3_1: C3.1 DA2.12 | length 34.6
  [1]Top w0.3: 64.25,47.913 DA2.12
  [1]Top w0.418: C3.1 45.353,28.268 ccw(c45.353,47.165) 64.25,47.165 64.25,47.913
NetC3_2: C3.2 DA1.8 L1.1 | length 7.6
  [1]Top w0.3: DA1.8@33.251,28.25 33.804,28.25
  [1]Top w0.418: 33.804,28.25 34.812,28.25 34.821,28.259 40.792,28.259 C3.2
NetC8_1: C8.1 DA2.9 | length 34.6
  [1]Top w0.3: 62.75,47.913 DA2.9
  [1]Top w0.418: C8.1 49.53,49.985 ccw(c49.53,52.423) 51.968,52.423 51.968,52.721 cw(c54.353,52.721) 54.353,55.105 cw(c54.353,52.546) 56.911,52.546 56.911,47.624 ccw(c59.831,47.618) 62.75,47.623 62.75,47.913
NetC8_2: C8.2 DA3.8 L3.1 | length 7.6
  [1]Top w0.3: DA3.8@33.251,49.992 33.804,49.992
  [1]Top w0.418: 33.804,49.992 34.809,49.992 34.813,49.989 40.814,49.989 C8.2
NetC9_1: C9.1 DA1.2 L2.2 | length 4.1
  [1]Top w0.3: 29.6,28.25 DA1.2
  [1]Top w0.418: C9.1 26.205,28.242 L2.2 ; L2.2@28.747,28.25 29.6,28.25
NetC9_2: C9.2 DA4.8 L4.1 | length 9.2
  [1]Top w0.3: DA4.8@15.921,28.244 16.474,28.244
  [1]Top w0.418: 16.474,28.244 L4.1 C9.2
NetC13_1: C13.1 R1.2 | length 4.3
  [1]Top w0.418: C13.1 R1.2
NetC13_2: C13.2 DA2.1 | length 12.5
  [1]Top w0.3: DA2.1 64.25,52.087
  [1]Top w0.418: 64.25,52.087 64.25,55.751 cw(c66.79,55.751) 66.79,58.291 C13.2
NetC16_1: C16.1 DA2.4 | length 34.6
  [1]Top w0.3: DA2.4 62.75,52.087
  [1]Top w0.418: C16.1 47.254,71.753 47.256,71.753 cw(c47.27,56.273) 62.75,56.273 62.75,52.087
NetC16_2: C16.2 DA5.8 L7.1 | length 7.6
  [1]Top w0.3: DA5.8 33.752,71.735
  [1]Top w0.418: 33.752,71.735 34.812,71.735 34.821,71.744 40.792,71.744 C16.2
NetC18_1: C18.1 DA3.2 L5.2 | length 4.2
  [1]Top w0.3: 29.697,50.007 DA3.2@30.25,50.007
  [1]Top w0.418: C18.1 26.066,49.991 28.617,49.991 L5.2 ; L5.2@28.626,50.007 29.697,50.007
NetC18_2: C18.2 DA6.8 L9.1 | length 9.2
  [1]Top w0.3: DA6.8@15.92,49.993 16.473,49.993
  [1]Top w0.418: 16.473,49.993 L9.1 ; L9.1@17.572,49.993 L9.1 ; C18.2 L9.1
NetC21_1: C21.1 DA5.2 L8.2 | length 4.2
  [1]Top w0.3: 29.75,71.735 DA5.2
  [1]Top w0.418: C21.1 26.205,71.743 L8.2@28.622,71.743 ; L8.2 28.88,71.746 28.88,71.743 29.743,71.743
NetC21_2: C21.2 DA7.8 L11.1 | length 9.2
  [1]Top w0.3: DA7.8@15.928,71.743 16.482,71.743
  [1]Top w0.418: 16.482,71.743 L11.1 C21.2
NetC22_1: C22.1 XW3.1 | length 69
  [1]Top w0.418: C22.1 XW3.1
NetC22_2: C22.2 DA2.15 | length 3.8
  [1]Top w0.3: DA2.15 65.587,50.25
  [1]Top w0.418: 65.587,50.25 C22.2
NetDA4_2: DA4.2 L6.2 XW1.1 | length 11.8
  [1]Top w0.3: 12.373,28.251 DA4.2
  [1]Top w0.418: XW1.1 L6.2 ; L6.2 12.366,28.257
NetDA6_2: DA6.2 L10.2 XW2.1 | length 11.8
  [1]Top w0.3: 12.418,49.993 12.425,49.987 DA6.2
  [1]Top w0.418: XW2.1 L10.2 12.418,49.993
NetDA7_2: DA7.2 L12.2 XW4.1 | length 11.8
  [1]Top w0.3: 12.384,71.747 DA7.2
  [1]Top w0.418: XW4.1 L12.2 12.374,71.757
pads on no net: DA1.11 DA1.12 DA3.11 DA3.12 DA4.11 DA4.12 DA5.11 DA5.12 DA6.11 DA6.12 DA7.11 DA7.12

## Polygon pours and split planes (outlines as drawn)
GND on [1]Top "GND_L01_P002" (solid, pour order 2): 0.2,0.2 0.2,99.8 139.8,99.8 139.8,0.2
GND on [4]Power "GND_L04_P004" (solid, remove dead copper, pour order 4): 0.2,0.2 0.2,99.8 139.8,99.8 139.8,0.2
GND on [2]MWGND "GND_L02_P005" (solid, pour order 5): 0.2,0.2 0.2,99.8 139.8,99.8 139.8,0.2
GND on [3]Signal "GND_L03_P007" (solid, pour order 7): 0.2,0.2 0.2,99.8 139.8,99.8 139.8,0.2

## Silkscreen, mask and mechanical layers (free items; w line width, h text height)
Top Overlay:
  text "ITMO switch" at 80.01,18.383 h8
Mechanical 1:
  lines w0.2: 0,0 63.5,0 63.5,87 ; 1.15,21.75 128.15,21.75 ; 1.151,28.251 31.75,28.251 ; 1.15,43.5 128.15,43.5 ; 1.15,50 31.743,50 31.751,49.993 ; 1.15,65.25 128.15,65.25 ; 1.15,71.75 31.736,71.75 31.751,71.735 ; 11.268,27.971 11.268,85.461 11.278,85.471 ; 14.326,82.347 14.412,82.26 34.823,82.26 ; 14.419,28.244 14.419,80.916 ; 16.104,58.725 16.153,58.675 34.765,58.675 ; 16.256,37.287 16.268,37.275 34.815,37.275 ; 17.577,81.839 17.579,81.837 17.579,28.141 ; 25.578,-58.014 25.578,41.986 ; 25.578,43.482 25.578,143.482 ; 31.75,0 31.75,87 ; 37.084,-35.967 37.084,64.033 ; 41.275,21.768 41.275,121.768 ; 101.778,24.486 101.778,42.621
  lines w0.254: 0,0 127,0 127,87 0,87 0,0
Mechanical 2:
  circle w0.013: c133.506,6.506 r2.65
  circle w0.013: c133.506,93.506 r2.65
  circle w0.013: c6.506,6.506 r2.65
  circle w0.013: c6.506,93.506 r2.65
  lines w0.013: 70.006,0.006 70.006,100.006 ; 0.006,0.006 140.006,0.006 140.006,100.006 0.006,100.006 0.006,0.006
  lines w0.2: 31.751,28.25 31.75,28.251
